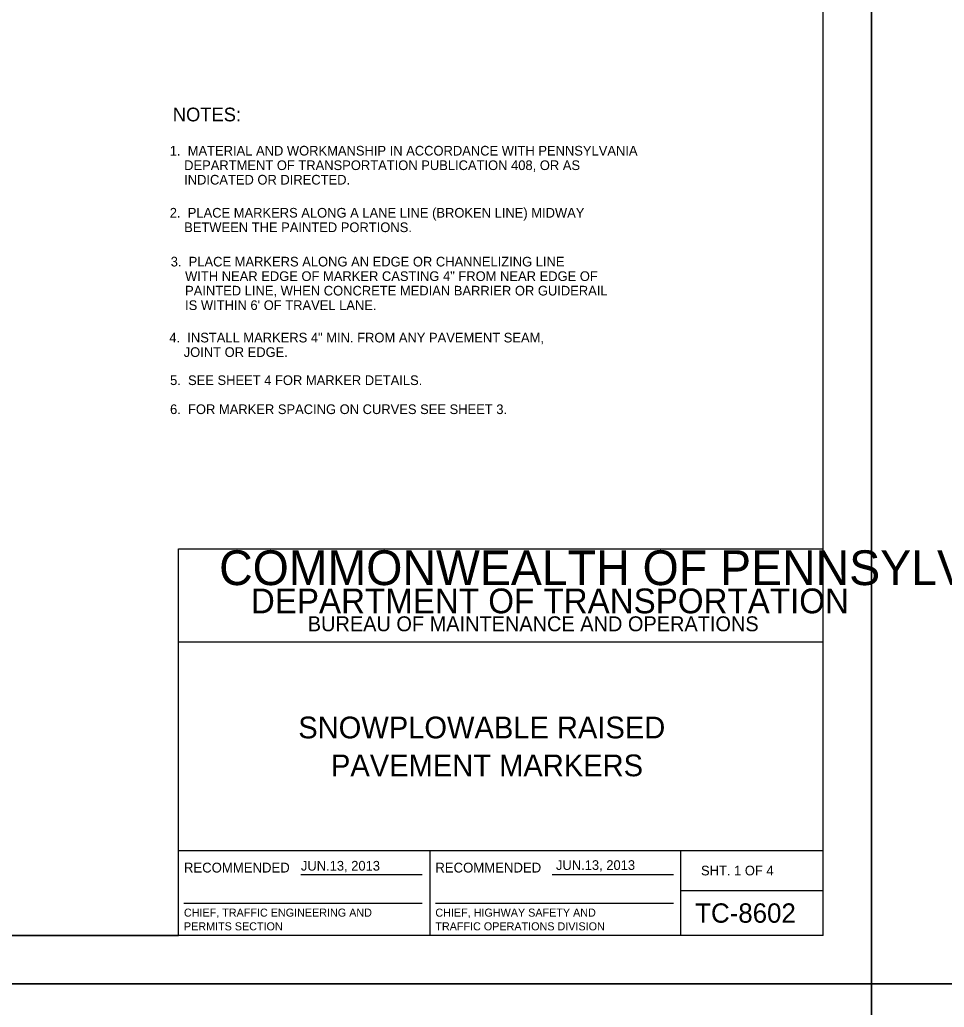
# Model space of a CAD drawing. Extents: x 639362 to 641108, y 298458 to 299646.
# Drawn here: x 639939.1 to 640225.9, y 299044.4 to 299350.7 of the extents above; entities that cross this region are included whole.
import ezdxf

# ---------------------------------------------------------------- set-up
doc = ezdxf.new("R2010")
doc.units = 0
for name, color, linetype in [('1', 7, 'Continuous'), ('2', 7, 'Continuous'), ('Level 1', 7, 'Continuous'), ('PLT-BNDY', 7, 'Continuous')]:
    doc.layers.add(name, color=color, linetype=linetype)

msp = doc.modelspace()

# ---------------------------------------------------------------- linework, layer by layer
at = {"layer": '1'}
for p, q in [((640188.31, 299066.63), (640188.31, 299630.63)), ((639988.31, 299066.63), (639988.31, 299186.63)), ((639988.31, 299186.63), (640188.31, 299186.63)), ((640188.31, 299157.63), (639988.31, 299157.63)), ((639988.31, 299093), (640188.31, 299093)), ((640066.31, 299093), (640066.31, 299066.63)), ((640144.19, 299066.63), (640144.19, 299093)), ((640026.24, 299085.57), (640063.87, 299085.57)), ((640104.24, 299085.57), (640141.87, 299085.57)), ((640144.19, 299080.63), (640188.31, 299080.63)), ((640188.31, 299066.63), (639402.31, 299066.63)), ((639402.31, 299066.63), (639988.31, 299066.63))]:
    msp.add_line(p, q, dxfattribs=at)
at = {"layer": 'Level 1'}
for p, q in [((639989.99, 299076.68), (640063.87, 299076.68)), ((640067.99, 299076.68), (640141.87, 299076.68))]:
    msp.add_line(p, q, dxfattribs=at)
at = {"layer": 'PLT-BNDY'}
for points in [[(639362.31, 299645.63), (640203.31, 299645.63), (640203.31, 299051.63), (639362.31, 299051.63)], [(640203.31, 299645.63), (641044.31, 299645.63), (641044.31, 299051.63), (640203.31, 299051.63)], [(639362.31, 299051.63), (640203.31, 299051.63), (640203.31, 298457.63), (639362.31, 298457.63)], [(640203.31, 299051.63), (641044.31, 299051.63), (641044.31, 298457.63), (640203.31, 298457.63)]]:
    msp.add_lwpolyline(points, close=True, dxfattribs=at)

# ---------------------------------------------------------------- texts
at = {"layer": '1'}
for s, height, p in [('COMMONWEALTH OF PENNSYLVANIA', 10.7828, (640000.9, 299175.36)), ('DEPARTMENT OF TRANSPORTATION', 7.6837, (640010.76, 299166.61)), ('BUREAU OF MAINTENANCE AND OPERATIONS', 4.6253, (640028.41, 299161.04)), ('SNOWPLOWABLE RAISED', 6.75, (640025.46, 299127.81)), ('PAVEMENT MARKERS', 6.75, (640035.61, 299116.06)), ('JUN.13, 2013', 3, (640026.28, 299086.8)), ('JUN.13, 2013', 3, (640105.41, 299087.01)), ('RECOMMENDED', 3.048, (639989.99, 299086.2)), ('RECOMMENDED', 3.048, (640067.99, 299086.2)), ('SHT. 1 OF 4', 3, (640150.4, 299085.31)), ('TC-8602', 6, (640148.6, 299070.63))]:
    msp.add_text(s, height=height, dxfattribs=at).set_placement(p)
at = {"layer": '2'}
for s, height, p in [('NOTES:', 4.25, (639986.54, 299319.21)), ('1.  MATERIAL AND WORKMANSHIP IN ACCORDANCE WITH PENNSYLVANIA', 3, (639985.6, 299308.6)), ('    DEPARTMENT OF TRANSPORTATION PUBLICATION 408, OR AS', 3, (639985.6, 299304.1)), ('    INDICATED OR DIRECTED.', 3, (639985.6, 299299.6)), ('2.  PLACE MARKERS ALONG A LANE LINE (BROKEN LINE) MIDWAY', 3, (639985.6, 299289.35)), ('    BETWEEN THE PAINTED PORTIONS.', 3, (639985.6, 299284.85)), ('3.  PLACE MARKERS ALONG AN EDGE OR CHANNELIZING LINE', 3, (639985.89, 299274.19)), ('    WITH NEAR EDGE OF MARKER CASTING 4" FROM NEAR EDGE OF ', 3, (639985.89, 299269.69)), ('    PAINTED LINE, WHEN CONCRETE MEDIAN BARRIER OR GUIDERAIL', 3, (639985.89, 299265.19)), ("    IS WITHIN 6' OF TRAVEL LANE.", 3, (639985.89, 299260.69)), ('4.  INSTALL MARKERS 4" MIN. FROM ANY PAVEMENT SEAM,', 3, (639985.46, 299250.63)), ('    JOINT OR EDGE.', 3, (639985.46, 299246.13)), ('5.  SEE SHEET 4 FOR MARKER DETAILS.', 3, (639985.69, 299237.41)), ('6.  FOR MARKER SPACING ON CURVES SEE SHEET 3.', 3, (639985.69, 299228.41))]:
    msp.add_text(s, height=height, dxfattribs=at).set_placement(p)
at = {"layer": 'Level 1'}
for s, p in [('CHIEF, TRAFFIC ENGINEERING AND', (639989.99, 299072.51)), ('CHIEF, HIGHWAY SAFETY AND', (640067.99, 299072.51)), ('PERMITS SECTION', (639989.99, 299068.26)), ('TRAFFIC OPERATIONS DIVISION', (640067.99, 299068.26))]:
    msp.add_text(s, height=2.5, dxfattribs=at).set_placement(p)

doc.saveas('drawing.dxf')
